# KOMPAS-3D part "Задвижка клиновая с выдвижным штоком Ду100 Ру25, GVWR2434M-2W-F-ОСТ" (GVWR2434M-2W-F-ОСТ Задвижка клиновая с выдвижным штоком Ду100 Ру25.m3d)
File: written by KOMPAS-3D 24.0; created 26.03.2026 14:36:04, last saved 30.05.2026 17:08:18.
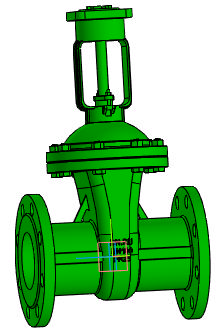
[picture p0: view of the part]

Document properties: Автор: R2D2; Полное имя файла: E:\Работа\Зайцев\GVWR2434M-2W-F-ОСТ Задвижка клиновая с выдвижным штоком DN.ru Ду50-300 Ру25\исходные материалы\DN100\DN100\GVWR2434M-2W-F-ОСТ Задвижка клиновая с выдвижным штоком Ду100 Ру25.m3d

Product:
- Part/product: Задвижка клиновая с выдвижным штоком Ду100 Ру25  | designation GVWR2434M-2W-F-ОСТ
    Масса: 32
    Раздел спецификации: Прочие изделия
    Примечание: D040-07588

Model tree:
1. Операция без истории:1

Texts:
  GVWR2434M-2W-F-ОСТ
